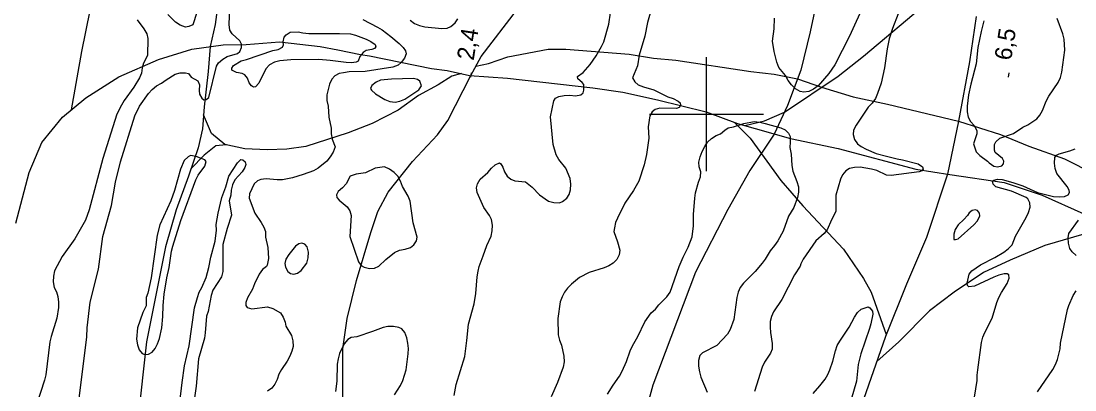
# Model space of a CAD drawing. Extents: x 282461 to 284471, y 5554090 to 5557646.
# Drawn here: x 282879.7 to 283064.7, y 5555551.7 to 5555616.3 of the extents above; entities that cross this region are included whole.
import ezdxf

# ---------------------------------------------------------------- set-up
doc = ezdxf.new("R2010")
doc.units = 0
for name, color, linetype in [('Niveau 1', 7, 'Continuous'), ('Niveau 2', 7, 'Continuous'), ('Niveau 22', 7, 'Continuous'), ('Niveau 3', 7, 'Continuous'), ('Niveau 61', 7, 'Continuous')]:
    doc.layers.add(name, color=color, linetype=linetype)

msp = doc.modelspace()

# ---------------------------------------------------------------- linework, layer by layer
at = {"layer": 'Niveau 1'}
for points in [[(283033.64, 5555617.61), (283032.63, 5555615.01), (283032.07, 5555613.22), (283031.69, 5555611.48), (283031.26, 5555608.14), (283030.65, 5555605.42), (283030.03, 5555603.63), (283029.64, 5555602.76), (283029.07, 5555601.95), (283028.38, 5555601.26), (283026.28, 5555598.07), (283025.82, 5555597.2), (283025.72, 5555596.45), (283025.96, 5555595.59), (283026.49, 5555594.79), (283027.13, 5555594.33), (283028, 5555593.87), (283029.79, 5555593.14), (283031.59, 5555592.63), (283033.44, 5555592.18), (283034.43, 5555592.02), (283037.15, 5555591.29), (283037.91, 5555590.77), (283038.03, 5555590.37), (283037.8, 5555590.08), (283037.34, 5555589.9), (283032.43, 5555589.24), (283031.57, 5555589.34), (283029.88, 5555590.14), (283028.96, 5555590.36), (283026.99, 5555590.7), (283026.01, 5555590.69), (283025.09, 5555590.51), (283024.45, 5555590.1), (283023.88, 5555589.41), (283023.55, 5555588.6), (283022.71, 5555585.82), (283022.68, 5555582.94), (283021.94, 5555581.5), (283021.21, 5555579.76), (283020.64, 5555579.12), (283019.21, 5555577.79), (283016.99, 5555574.6), (283016.54, 5555573.79), (283016.43, 5555573.39), (283015.46, 5555571.83), (283013.25, 5555567.55), (283011.77, 5555565.35), (283011.43, 5555564.54), (283011.21, 5555563.67), (283011.17, 5555562.69), (283011.23, 5555561.77), (283011.54, 5555559.81), (283011.55, 5555558.83), (283011.27, 5555558.14), (283010.19, 5555556.52), (283009.79, 5555555.65), (283008.45, 5555551.38)], [(283047.04, 5555550.43), (283047.53, 5555553.31), (283047.52, 5555554.29), (283047.63, 5555555.22), (283048.27, 5555560), (283048.49, 5555560.93), (283048.83, 5555561.74), (283050.13, 5555564.28), (283050.97, 5555567), (283051.31, 5555567.86), (283051.76, 5555568.73), (283052.79, 5555570.35), (283053.12, 5555571.28), (283053.06, 5555571.85), (283052.77, 5555572.02), (283052.25, 5555572.02), (283051.33, 5555571.78), (283050.46, 5555571.43), (283047.01, 5555569.85), (283046.03, 5555569.73), (283045.8, 5555569.96), (283045.74, 5555570.42), (283046.13, 5555571.98), (283046.58, 5555572.56), (283048.07, 5555573.61), (283050.6, 5555574.89), (283052.21, 5555575.83), (283052.96, 5555576.41), (283053.64, 5555577.1), (283054.26, 5555578.66), (283056.13, 5555581.91), (283056.53, 5555582.77), (283056.81, 5555583.7), (283056.74, 5555584.5), (283056.39, 5555585.19), (283056.1, 5555585.42), (283053.55, 5555586.5), (283050.77, 5555587.29), (283050.3, 5555587.75), (283050.18, 5555588.26), (283050.41, 5555588.44), (283051.1, 5555588.62), (283051.91, 5555588.56), (283053.76, 5555588.06), (283055.5, 5555587.44), (283058.11, 5555586.3), (283060.89, 5555585.57), (283061.88, 5555585.52), (283062.86, 5555585.58), (283063.49, 5555585.88), (283063.72, 5555586.28), (283063.65, 5555586.68), (283063.3, 5555587.32), (283061.49, 5555589.61), (283061.19, 5555590.47), (283061.06, 5555591.45), (283061.11, 5555592.43), (283061.4, 5555592.84), (283061.91, 5555593.07), (283063.76, 5555593.6), (283064.68, 5555593.96)]]:
    msp.add_lwpolyline(points, dxfattribs=at)
at = {"layer": 'Niveau 2'}
for points in [[(282900.54, 5555601.43), (282902.07, 5555603.64), (282902.76, 5555604.34), (282903.5, 5555604.98), (282904.37, 5555605.44), (282905.17, 5555606.03), (282906.78, 5555607.02), (282907.64, 5555607.26), (282908.62, 5555607.26), (282909.09, 5555607.15), (282909.61, 5555606.52), (282910.78, 5555605.84), (282911.02, 5555605.14), (282910.97, 5555604.16), (282911.03, 5555603.53), (282911.44, 5555602.84), (282911.79, 5555602.55), (282912.2, 5555602.56), (282912.66, 5555602.96), (282914.04, 5555608.4), (282914.38, 5555609.04), (282915.13, 5555609.68), (282915.93, 5555610.14), (282917.72, 5555610.67), (282918.12, 5555610.97), (282918.4, 5555611.72), (282918.4, 5555612.3), (282918.1, 5555612.87), (282916.76, 5555614.07), (282916.4, 5555614.76), (282916.28, 5555615.74), (282916.36, 5555618.63)], [(282990.43, 5555618.72), (282989.65, 5555616.06)], [(283027.82, 5555619.56), (283025.11, 5555613.71), (283022.56, 5555608.68), (283021.47, 5555607.17), (283019.59, 5555604.96), (283018.79, 5555604.38), (283017.98, 5555603.97), (283017.11, 5555603.85), (283016.42, 5555603.96), (283015.61, 5555604.47), (283014.9, 5555605.16), (283014.32, 5555605.91), (283013.85, 5555606.77), (283012.73, 5555608.2), (283012.38, 5555609.12), (283011.9, 5555610.97), (283011.59, 5555612.81), (283011.86, 5555614.95), (283011.95, 5555616.85)], [(282900.13, 5555616.53), (282901.3, 5555614.98), (282901.78, 5555614.11), (282901.96, 5555613.25), (282901.93, 5555610.3), (282901.2, 5555608.97), (282900.97, 5555608.16), (282900.87, 5555607.18), (282900.53, 5555606.36), (282899.51, 5555604.74), (282897.85, 5555602.42), (282897.34, 5555601.61), (282896.55, 5555600.04), (282894.09, 5555592.23), (282891.7, 5555583.26), (282891.02, 5555581.46), (282889.15, 5555578.16), (282886.93, 5555575.08), (282885.63, 5555572.53)], [(282910.59, 5555617.84), (282909.86, 5555615.7), (282909.17, 5555615.35), (282908.59, 5555615.29), (282907.67, 5555615.63), (282906.85, 5555616.14), (282905.51, 5555617.46)], [(282939.68, 5555616.6), (282942.3, 5555615.29), (282943.11, 5555614.78), (282944.63, 5555613.64), (282946.09, 5555612.38), (282946.79, 5555611.69), (282947.2, 5555611.11), (282947.32, 5555610.59), (282947.04, 5555609.84), (282946.41, 5555609.09), (282945.89, 5555608.62), (282944.97, 5555608.27), (282940.13, 5555607.48), (282937.29, 5555607.41), (282936.31, 5555607.28), (282935.56, 5555607.16), (282934.81, 5555606.75), (282934.24, 5555606.12), (282933.85, 5555605.25), (282933.4, 5555603.4), (282933.42, 5555602.42), (282933.6, 5555601.44), (282933.74, 5555599.47), (282934.16, 5555597.57), (282934.17, 5555596.59), (282934.3, 5555595.61), (282934.83, 5555594.29), (282934.49, 5555593.36), (282933.98, 5555592.55), (282933.41, 5555591.8), (282931.87, 5555590.57), (282931.06, 5555590.11), (282929.22, 5555589.46), (282927.37, 5555588.87), (282925.64, 5555588.51), (282924.66, 5555588.5), (282922.75, 5555588.66), (282921.83, 5555588.54), (282921.2, 5555588.31), (282920.62, 5555587.78), (282919.83, 5555586.05), (282919.78, 5555585.29), (282920.74, 5555582.65), (282921.85, 5555581.04), (282922.32, 5555580.23), (282922.62, 5555579.43), (282922.63, 5555578.45), (282923.05, 5555576.66), (282923.13, 5555574.7), (282922.91, 5555573.54), (282922.8, 5555573.31)], [(282948.04, 5555616.46), (282948.79, 5555615.89), (282949.67, 5555615.55), (282950.59, 5555615.32), (282953.55, 5555615), (282954.53, 5555615.06), (282955.16, 5555615.36), (282955.91, 5555616), (282956.37, 5555616.75)], [(282955.76, 5555550.69), (282956.08, 5555552.65), (282957.59, 5555557.57), (282957.97, 5555560.34), (282958.23, 5555563.23), (282959.23, 5555566.75), (282959.56, 5555568.6), (282959.76, 5555571.49), (282959.92, 5555572.47), (282960.14, 5555573.34), (282960.82, 5555575.19), (282961.49, 5555576.98), (282962.23, 5555578.66), (282962.39, 5555579.59), (282962.44, 5555580.57), (282962.31, 5555581.55), (282961.96, 5555582.24), (282960.96, 5555583.68), (282959.78, 5555586.26), (282959.65, 5555587.13), (282959.82, 5555587.82), (282960.27, 5555588.63), (282961.65, 5555589.8), (282962.28, 5555590.55), (282962.91, 5555591.14), (282963.71, 5555591.49), (282963.94, 5555591.32), (282964.3, 5555590.74), (282964.54, 5555589.88), (282965.01, 5555589.13), (282965.65, 5555588.61), (282966.4, 5555588.33), (282968.26, 5555588.17), (282969.42, 5555587.2), (282970.71, 5555585.88), (282972.28, 5555584.79), (282973.21, 5555584.51), (282974.19, 5555584.46), (282974.77, 5555584.69), (282975.51, 5555585.28), (282975.91, 5555585.91), (282976.13, 5555586.78), (282976.18, 5555587.76), (282976.11, 5555588.74), (282975.34, 5555590.53), (282974.11, 5555592.08), (282973.64, 5555592.88), (282973.1, 5555594.67), (282972.65, 5555599.52), (282973.2, 5555602.35), (282973.54, 5555602.81), (282974.11, 5555603.11), (282975.04, 5555603.28), (282976.02, 5555603.35), (282977, 5555603.24), (282977.98, 5555603.42), (282978.39, 5555603.77), (282978.5, 5555604.23), (282978.49, 5555605.21), (282978.19, 5555605.56), (282977.43, 5555606.19), (282977.37, 5555606.59), (282978.35, 5555607.29), (282979.61, 5555608.74), (282980.63, 5555610.25), (282981.6, 5555611.88), (282981.99, 5555612.69), (282982.89, 5555615.81), (282983.15, 5555617.78)], [(283048.69, 5555616.36), (283048.19, 5555614.51), (283047.64, 5555611.69), (283047.32, 5555608.86), (283046.38, 5555605.28), (283045.99, 5555603.38), (283045.78, 5555601.42), (283045.73, 5555600.44), (283045.92, 5555599.46), (283046.33, 5555598.71), (283046.97, 5555598.03), (283047.44, 5555597.17), (283047.45, 5555596.59), (283046.89, 5555594.8), (283047.01, 5555594.28), (283047.36, 5555593.42), (283047.95, 5555592.79), (283049.34, 5555591.77)], [(283049.34, 5555591.77), (283049.63, 5555591.48), (283050.45, 5555590.91), (283051.08, 5555590.8), (283051.83, 5555590.98), (283052.12, 5555591.32), (283052.17, 5555591.78), (283051.94, 5555592.24), (283050.66, 5555593.27), (283050.54, 5555593.73), (283050.53, 5555594.71), (283050.81, 5555595.17), (283051.5, 5555595.81), (283053.91, 5555596.64), (283055.52, 5555597.74), (283056.38, 5555598.15), (283057.98, 5555599.2), (283058.5, 5555599.84), (283058.95, 5555600.65), (283059.63, 5555602.32), (283060.08, 5555603.19), (283061.73, 5555605.56), (283062.13, 5555606.43), (283062.35, 5555607.35), (283062.89, 5555611.22), (283062.75, 5555613.18), (283062.51, 5555614.1), (283061.56, 5555616.8)], [(282929.17, 5555614.25), (282930.21, 5555614.14), (282935.59, 5555614.18), (282937.55, 5555614.08), (282938.42, 5555613.85), (282940.28, 5555613.17), (282941.09, 5555612.77), (282941.9, 5555612.2), (282941.97, 5555611.8), (282941.74, 5555611.51), (282941.28, 5555611.33), (282940.3, 5555611.15), (282939.78, 5555610.8), (282939.21, 5555610.11), (282938.87, 5555609.3), (282938.53, 5555609.12), (282937.72, 5555609), (282936.8, 5555609.05), (282933.96, 5555609.44), (282932, 5555609.6), (282927.09, 5555609.56), (282925.12, 5555609.37), (282924.2, 5555609.14), (282923.34, 5555608.67), (282922.66, 5555607.97), (282921.47, 5555605.43), (282920.9, 5555604.79), (282920.5, 5555604.73), (282920.15, 5555604.96), (282919.74, 5555605.53), (282919.5, 5555606.34), (282919.03, 5555606.91), (282918.51, 5555607.14), (282917.52, 5555607.3), (282916.71, 5555607.7), (282916.71, 5555608.05), (282916.99, 5555608.57), (282918.37, 5555609.38), (282919.29, 5555609.62), (282923.89, 5555611.15), (282924.87, 5555611.33), (282925.62, 5555611.74), (282925.79, 5555612.15), (282925.72, 5555612.72), (282925.89, 5555613.53), (282926.23, 5555613.94), (282926.98, 5555614.41), (282928.36, 5555614.47), (282929.17, 5555614.25)], [(282989.65, 5555616.06), (282989.21, 5555613.69), (282988.21, 5555610.34), (282987.88, 5555608.49), (282987.03, 5555606.41), (282987.45, 5555605.66), (282988.03, 5555605.14), (282988.96, 5555604.8), (282990.75, 5555604.3), (282992.38, 5555603.44), (282993.25, 5555603.05), (282994.18, 5555602.76), (282995.05, 5555602.31), (282995.4, 5555602.02), (282995.46, 5555601.62), (282995.24, 5555601.21), (282994.72, 5555600.98), (282991.83, 5555601.07), (282991.02, 5555600.84), (282990.45, 5555600.43), (282990.05, 5555599.74), (282989.78, 5555597.77), (282989.92, 5555595.81), (282989.49, 5555592.92), (282989.1, 5555591.13), (282988.15, 5555588.3), (282987.18, 5555586.62), (282985.7, 5555584.42), (282984.4, 5555581.81), (282984.06, 5555581), (282983.84, 5555580.08), (282983.73, 5555579.45), (282984.39, 5555577.66), (282984.81, 5555576.17), (282984.7, 5555575.36), (282984.3, 5555574.55), (282983.62, 5555573.91), (282982.87, 5555573.44), (282982.07, 5555573.09), (282979.42, 5555572.26), (282977.75, 5555571.39), (282976.32, 5555570.22), (282975.63, 5555569.53), (282975.12, 5555568.83), (282974.67, 5555568.02), (282974.33, 5555567.1), (282973.95, 5555564.21), (282973.98, 5555561.33), (282974.23, 5555560.41), (282974.58, 5555559.54), (282974.95, 5555557.59), (282975.02, 5555556.61), (282974.85, 5555555.68), (282973.84, 5555552.97), (282972.77, 5555550.48)], [(282950.01, 5555604.98), (282949.71, 5555605.79), (282949.3, 5555606.07), (282948.61, 5555606.24), (282944.73, 5555606.15), (282942.82, 5555605.97), (282942.07, 5555605.62), (282941.27, 5555605.03), (282941.04, 5555604.51), (282941.22, 5555604.22), (282941.92, 5555603.59), (282943.55, 5555602.56), (282944.43, 5555602.22), (282945.41, 5555602.12), (282946.22, 5555602.29), (282947.08, 5555602.65), (282949.55, 5555604.28), (282950.01, 5555604.98)], [(282889.94, 5555550.18), (282891.26, 5555560.98), (282891.36, 5555562.59), (282891.89, 5555567.04), (282893.33, 5555572.82), (282894.08, 5555578.6), (282895.58, 5555584.03), (282896.29, 5555588.07), (282897.17, 5555591.66), (282899.69, 5555599.7), (282900.54, 5555601.43)], [(283000.21, 5555595.08), (283000.9, 5555595.77), (283001.7, 5555596.3), (283002.45, 5555596.59), (283003.2, 5555597.23), (283003.83, 5555597.64), (283004.75, 5555597.82), (283006.59, 5555598.35), (283008.38, 5555598.71), (283009.37, 5555598.6), (283010.29, 5555598.38), (283013.08, 5555597.59), (283013.83, 5555597.25), (283014.41, 5555596.68), (283014.71, 5555596.1), (283014.72, 5555595.12), (283014.61, 5555594.2), (283014.86, 5555592.99), (283014.99, 5555591.03), (283015.18, 5555590.05), (283015.89, 5555588.21), (283016.13, 5555587.28), (283016.14, 5555586.36), (283015.98, 5555585.38), (283015.36, 5555583.64), (283014.39, 5555582.14), (283013.49, 5555579.48), (283012.53, 5555577.8), (283011.96, 5555576.99), (283011.16, 5555576.06), (283010.31, 5555574.61), (283009.79, 5555573.92), (283008.54, 5555572.41), (283006.48, 5555570.37), (283005.91, 5555569.62), (283005.57, 5555568.81), (283005.35, 5555567.89), (283004.81, 5555564.02), (283004.19, 5555562.28), (283003.68, 5555561.47), (283001.85, 5555559.44), (282999.33, 5555558.16), (282998.87, 5555557.69), (282998.59, 5555556.82), (282998.6, 5555555.84), (282998.78, 5555554.86), (282999.02, 5555553.94), (283000.15, 5555551.3)], [(282982.64, 5555550.95), (282983.61, 5555552.51), (282984.75, 5555554.08), (282985.2, 5555554.95), (282985.99, 5555556.68), (282986.61, 5555558.53), (282987, 5555559.4), (282987.97, 5555561.02), (282989.21, 5555563.62), (282990.3, 5555565.19), (282991.04, 5555565.83), (282991.67, 5555566.58), (282993.04, 5555567.97), (282993.61, 5555568.79), (282995.24, 5555573.3), (282995.91, 5555574.97), (282996.82, 5555576.71), (282997.5, 5555578.5), (282997.71, 5555580.46), (282997.74, 5555582.43), (282997.94, 5555585.31), (282998.11, 5555586.24), (282998.61, 5555588.09), (282998.95, 5555589.01), (282999, 5555589.88), (282998.75, 5555590.8), (282998.69, 5555591.6), (282998.91, 5555592.53), (282999.25, 5555593.45), (282999.7, 5555594.32), (283000.21, 5555595.08)], [(282901.67, 5555566.42), (282901.1, 5555565.26), (282900.15, 5555562.54), (282899.99, 5555560.58), (282900.18, 5555559.6), (282900.48, 5555558.73), (282901, 5555558.05), (282901.47, 5555557.88), (282902.1, 5555557.94), (282902.73, 5555558.29), (282903.25, 5555558.93), (282903.7, 5555559.79), (282904.04, 5555560.72), (282904.42, 5555562.57), (282904.63, 5555564.53), (282904.67, 5555566.49), (282904.82, 5555568.46), (282905.31, 5555571.35), (282905.75, 5555573.14), (282906.13, 5555576.02), (282906.35, 5555576.89), (282907.8, 5555581.4), (282910.38, 5555588.52), (282910.84, 5555589.33), (282911.98, 5555590.9), (282912.2, 5555591.71), (282911.97, 5555591.99), (282910.46, 5555592.62), (282909.47, 5555592.78), (282909.07, 5555592.55), (282908.33, 5555591.91), (282907.71, 5555590.35), (282906.65, 5555586.65), (282906.03, 5555584.85), (282904.11, 5555580.63), (282903.61, 5555578.78), (282902.54, 5555571.33), (282901.99, 5555568.67), (282901.71, 5555567.86), (282901.67, 5555566.42)], [(282906.46, 5555540.17), (282908, 5555552.98), (282908.43, 5555555.92), (282909.26, 5555559.39), (282910.17, 5555566.08), (282910.67, 5555567.87), (282911.01, 5555568.79), (282911.46, 5555569.66), (282912.19, 5555571.4), (282912.69, 5555573.13), (282913.02, 5555574.98), (282913.8, 5555577.75), (282914.01, 5555579.71), (282914, 5555580.69), (282914.32, 5555582.66), (282914.98, 5555585.43), (282915.66, 5555587.28), (282916.22, 5555589.13), (282917.69, 5555591.5), (282918.32, 5555592.08), (282918.67, 5555592.03), (282919.08, 5555591.68), (282919.2, 5555591.22), (282919.03, 5555590.65), (282918.52, 5555589.89), (282917.26, 5555588.5), (282916.81, 5555587.63), (282916.59, 5555586.71), (282916.54, 5555585.84), (282916.26, 5555584.8)], [(282937.51, 5555589.12), (282936.77, 5555587.79), (282936.14, 5555587.09), (282935.39, 5555586.45), (282935.11, 5555585.87), (282935.17, 5555585.41), (282935.53, 5555584.95), (282936.98, 5555583.75), (282937.45, 5555583.06), (282937.69, 5555582.25), (282937.44, 5555578.55), (282938.94, 5555574.11), (282939.41, 5555573.48), (282939.93, 5555573.2), (282940.86, 5555572.97), (282941.78, 5555573.04), (282942.53, 5555573.39), (282943.74, 5555574.55), (282945.28, 5555575.77), (282946.15, 5555576.19), (282947.13, 5555576.37), (282948.05, 5555576.66), (282948.68, 5555577.13), (282949.14, 5555577.82), (282949.25, 5555578.46), (282948.53, 5555580.94), (282948.02, 5555584.75), (282947.67, 5555585.67), (282946.67, 5555587.34), (282946.31, 5555588.26), (282945.84, 5555589.12), (282945.19, 5555589.81), (282944.38, 5555590.38), (282943.5, 5555590.78), (282941.89, 5555590.54), (282940.16, 5555589.72), (282938.54, 5555589.47), (282937.51, 5555589.12)], [(282916.26, 5555584.8), (282916.69, 5555582.33), (282915.91, 5555579.96), (282915.13, 5555577.18), (282915.12, 5555572.46), (282914.9, 5555571.53), (282913.37, 5555569.16), (282913.09, 5555568.23), (282912.54, 5555565.4), (282912.26, 5555564.59), (282912.06, 5555561.71), (282911.9, 5555560.73), (282910.9, 5555557.15), (282910.49, 5555552.36), (282910.06, 5555549.48)], [(283045.18, 5555581.54), (283044.2, 5555580.61), (283043.64, 5555579.8), (283043.41, 5555578.99), (283043.42, 5555578.07), (283043.71, 5555578.02), (283044.17, 5555578.19), (283046.92, 5555580.63), (283047.55, 5555581.33), (283048, 5555582.19), (283047.94, 5555582.65), (283047.58, 5555583.11), (283047.18, 5555583.22), (283046.6, 5555583.11), (283046.09, 5555582.7), (283045.8, 5555582.24), (283045.18, 5555581.54)], [(283064.87, 5555575.22), (283064.17, 5555575.91), (283063.76, 5555576.48), (283063.52, 5555577.4), (283063.45, 5555578.32), (283063.62, 5555579.07), (283065.27, 5555581.45)], [(282930.13, 5555574.81), (282930.17, 5555575.84), (282929.93, 5555576.77), (282929.52, 5555577.22), (282929, 5555577.39), (282928.48, 5555577.28), (282927.91, 5555576.87), (282926.71, 5555575.42), (282926.2, 5555574.61), (282926.03, 5555573.85), (282926.15, 5555573.22), (282926.57, 5555572.41), (282927.03, 5555572.07), (282927.61, 5555571.96), (282928.25, 5555572.14), (282928.88, 5555572.6), (282929.9, 5555573.88), (282930.13, 5555574.81)], [(282885.63, 5555572.53), (282885.41, 5555571.61), (282885.36, 5555570.63), (282885.54, 5555569.65), (282885.96, 5555568.9), (282886.2, 5555568.03), (282886.32, 5555567.05), (282886.33, 5555566.13), (282886.01, 5555564.28), (282885, 5555561.04), (282884.78, 5555560.11), (282884.09, 5555554.34), (282883.87, 5555553.41), (282882.41, 5555548.9), (282880.68, 5555537.92), (282879.96, 5555535.31), (282879.35, 5555532.66)], [(282922.8, 5555573.31), (282922.11, 5555572.79), (282921.54, 5555571.98), (282920.69, 5555570.3), (282920.36, 5555569.37), (282919.45, 5555567.81), (282919.17, 5555567), (282919.18, 5555566.48), (282919.41, 5555566.13), (282920.22, 5555565.91), (282922.99, 5555566.22), (282923.92, 5555565.93), (282925.26, 5555565.19), (282925.73, 5555564.45), (282926.08, 5555563.53), (282926.21, 5555562.83), (282927.21, 5555561.22), (282927.45, 5555560.3), (282927.46, 5555559.32), (282927.24, 5555558.46), (282926.9, 5555557.59), (282926.45, 5555556.72), (282925.42, 5555555.27), (282924.97, 5555554.46), (282924.69, 5555553.53), (282924.29, 5555552.67), (282923.72, 5555551.97), (282922.98, 5555551.44)], [(283058.12, 5555551.35), (283060.79, 5555555.29), (283061.25, 5555556.16), (283061.59, 5555557.02), (283062.09, 5555558.87), (283062.14, 5555559.85), (283063.35, 5555565.75), (283063.57, 5555566.5), (283064.36, 5555568.23), (283064.88, 5555569.04)], [(283018.71, 5555551.07), (283019.91, 5555552.4), (283020.82, 5555553.56), (283021.33, 5555554.37), (283021.67, 5555555.23), (283022.17, 5555556.73), (283022.62, 5555558.52), (283022.95, 5555559.45), (283023.41, 5555560.25), (283025.05, 5555562.68), (283025.96, 5555564.42), (283026.53, 5555565.23), (283027.16, 5555565.81), (283028.37, 5555566.22), (283028.66, 5555566.05), (283029.12, 5555565.48), (283029.19, 5555564.96), (283028.86, 5555563.29), (283028.64, 5555562.42), (283027.12, 5555557.98), (283026.62, 5555556.13), (283026.31, 5555553.19), (283024.97, 5555548.58)], [(282945.25, 5555550.81), (282946.33, 5555552.45), (282946.73, 5555553.32), (282947.29, 5555555.19), (282947.66, 5555558.03), (282947.7, 5555558.96), (282947.63, 5555559.89), (282947.45, 5555560.82), (282947.09, 5555561.74), (282946.56, 5555562.37), (282946.03, 5555562.6), (282945.1, 5555562.82), (282944.12, 5555562.81), (282943.25, 5555562.62), (282941.41, 5555561.91), (282938.63, 5555561), (282937.65, 5555560.87), (282937.08, 5555560.52), (282936.45, 5555559.76), (282935.6, 5555558.06), (282935.38, 5555557.13), (282935.22, 5555556.2), (282935.14, 5555553.24), (282934.93, 5555551.38)]]:
    msp.add_lwpolyline(points, dxfattribs=at)
at = {"layer": 'Niveau 22'}
for points in [[(282919.26, 5555737.83), (282916.74, 5555724.97), (282913.49, 5555714.88), (282909.91, 5555702.94), (282906.25, 5555687.53), (282900.1, 5555657.19), (282896.87, 5555640.64), (282893.33, 5555625.71), (282890.36, 5555611.01), (282888.54, 5555600.75)], [(283006.74, 5555598.01), (283010.21, 5555598.84), (283013.68, 5555600.36), (283023.12, 5555606.68), (283027.55, 5555610.2), (283038.96, 5555619.77), (283048.26, 5555625.7), (283051.18, 5555627.79), (283062.16, 5555635.01), (283068.11, 5555638.04), (283074.18, 5555640.61), (283079.68, 5555642.14), (283091.29, 5555644.98), (283097.59, 5555646.27), (283104.31, 5555647.44)], [(283020.57, 5555625.42), (283018.18, 5555614.44), (283016.55, 5555607.75), (283014.23, 5555601.52), (283011.86, 5555596.52), (283007.6, 5555590.15), (283003.74, 5555583.31), (282998.07, 5555572.31), (282990.61, 5555552.51), (282989.05, 5555546.96)], [(282914.24, 5555619.21), (282913.82, 5555615.74), (282912.91, 5555611.86), (282912.55, 5555607.49), (282911.87, 5555601.27), (282911.57, 5555597.46), (282910.79, 5555594.11), (282909.11, 5555589.14), (282906.98, 5555583.24), (282905.09, 5555576.76), (282901.73, 5555560.1), (282900.21, 5555546.38), (282898.68, 5555538.41), (282897.46, 5555529.21), (282894.69, 5555511.97), (282894.12, 5555507.78), (282892.52, 5555501.96), (282890.31, 5555493.3), (282886.59, 5555480.28), (282881.45, 5555463.65), (282879.76, 5555456.08), (282880.02, 5555453.33)], [(282936.3, 5555540.89), (282936.17, 5555553.13), (282936.22, 5555558.9), (282936.98, 5555564.22), (282938.58, 5555570.84), (282941.1, 5555579.27), (282942.33, 5555582.97), (282944.15, 5555586.34), (282948.43, 5555591.7), (282952.83, 5555596.37), (282954.65, 5555598.92), (282958.64, 5555606.8), (282960.5, 5555610.15), (282966.83, 5555618.42)], [(283047.36, 5555617.16), (283046.17, 5555609.2), (283044.22, 5555598.8), (283042.3, 5555589.49), (283038.61, 5555578.39), (283035.11, 5555570.19), (283031.4, 5555561.06), (283027.17, 5555548.85), (283023.97, 5555538.49), (283018.68, 5555514.63), (283015.92, 5555502.75), (283010.33, 5555480.8), (283001.17, 5555445.7), (282997.2, 5555431.92), (282994.29, 5555419.31)], [(282878.82, 5555580.92), (282881.14, 5555589.77), (282883.39, 5555595.02), (282887, 5555599.47), (282891.08, 5555602.87), (282896.89, 5555606.53), (282903.86, 5555609.62), (282909.69, 5555611.42), (282915.19, 5555612.18), (282919.24, 5555612.2), (282925.08, 5555612.7), (282932.21, 5555611.85), (282935.34, 5555611.31), (282939.29, 5555610.46), (282940.86, 5555610.25), (282951.74, 5555608), (282954.53, 5555607.69), (282958.43, 5555606.82), (282965.09, 5555606.31), (282980.09, 5555604.61), (282985.36, 5555603.85), (282991.44, 5555602.53), (282999.96, 5555600.42), (283005.43, 5555598.4), (283014.73, 5555595.73), (283023.13, 5555593.97), (283036.74, 5555590.4), (283042.69, 5555589.43), (283052.25, 5555588.05), (283058.93, 5555585.82), (283066.21, 5555582.56)], [(282959.54, 5555608.43), (282961.78, 5555608.89), (282965.13, 5555610.07), (282972.22, 5555611.41), (282975.35, 5555611.43), (282986.42, 5555610.53), (282990.73, 5555609.8), (282994.66, 5555609.48), (283007.81, 5555607.48), (283011.86, 5555607.05), (283015.99, 5555606.23), (283020.18, 5555604.72), (283025.75, 5555603.08), (283031.77, 5555601.79), (283044.22, 5555598.8), (283051.61, 5555596.45), (283056.57, 5555594.39), (283062.85, 5555592.19), (283068.02, 5555589.53)], [(282957.01, 5555607.14), (282955.34, 5555606.7), (282952.93, 5555605.18), (282949.48, 5555603.3), (282945.92, 5555600.74), (282941.32, 5555598.4), (282937.11, 5555596.77), (282929.68, 5555594.35), (282926.39, 5555593.88), (282922.93, 5555593.74), (282918.99, 5555593.94), (282915.51, 5555594.69), (282913.18, 5555596.64), (282911.76, 5555599.9)], [(283004.93, 5555598.58), (283007.7, 5555595.82), (283013.07, 5555588.4), (283016.9, 5555583.97), (283024.06, 5555576.38), (283027.58, 5555571.22), (283028.91, 5555568.84), (283031.53, 5555561.39)], [(282915.74, 5555594.64), (282913.91, 5555594.47), (282911.84, 5555592.84), (282909.55, 5555590.44)], [(283075.88, 5555580.9), (283070.85, 5555580.3), (283059.36, 5555577.02), (283053.28, 5555574.4), (283048.59, 5555572.25), (283043.45, 5555568.83), (283039.13, 5555565.53), (283033.79, 5555560.14), (283029.88, 5555556.68)]]:
    msp.add_lwpolyline(points, dxfattribs=at)
at = {"layer": 'Niveau 3'}
for p, q in [((282958.67, 5555606.48), (282958.79, 5555607.27)), ((283052.99, 5555606.48), (283053.11, 5555607.27))]:
    msp.add_line(p, q, dxfattribs=at)
at = {"layer": 'Niveau 61'}
for points in [[(283000, 5555590), (283000, 5555610)], [(282990, 5555600), (283010, 5555600)]]:
    msp.add_lwpolyline(points, dxfattribs=at)

# ---------------------------------------------------------------- texts
at = {"layer": 'Niveau 3'}
for s, p in [('2,4  ', (282959.15, 5555609.32)), ('6,5  ', (283053.47, 5555609.32))]:
    msp.add_text(s, height=3, rotation=81.0957, dxfattribs=at).set_placement(p)

doc.saveas('drawing.dxf')
